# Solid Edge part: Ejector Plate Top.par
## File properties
Author: davee
Template: Normal.par
Last saved by: davee
Revision: 9
Application: Solid Edge
Accuracy: 0.990
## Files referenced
..\Loose Support Mould.asm
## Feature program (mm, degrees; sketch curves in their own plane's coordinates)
sketch for "unnamed Protrusion 1" plane through (0, 0, 0) normal (0, 0, 1) x-axis (1, 0, 0)
  line (-62.5, -100) -> (62.5, -100)
  line (62.5, -100) -> (62.5, 100)
  line (62.5, 100) -> (-62.5, 100)
  line (-62.5, 100) -> (-62.5, -100)
  dimension (linear) = 62.5
  dimension (linear) = 62.5
extrude "unnamed Protrusion 1" add finite 16 along -normal
sketch for "Hole_1" plane through (0, 0, 0) normal (0, 0, 1) x-axis (1, 0, 0)
  hole centre (54, 89) bore radius 2.4585
hole "Hole_1" through  ThreadDepth = 2 mm
sketch for "unnamed Hole 1" plane through (0, 0, 0) normal (0, 0, 1) x-axis (1, 0, 0)
  hole centre (54, -89) bore radius 2.4585
hole "unnamed Hole 1" through
sketch for "unnamed Hole 2" plane through (0, 0, 0) normal (0, 0, 1) x-axis (1, 0, 0)
  hole centre (-54, -89) bore radius 2.4585
hole "unnamed Hole 2" through
sketch for "unnamed Hole 3" plane through (0, 0, 0) normal (0, 0, 1) x-axis (1, 0, 0)
  hole centre (-54, 89) bore radius 2.4585
  dimension (linear) = 54
hole "unnamed Hole 3" through
pattern "unnamed Pattern 1" of "Hole_1", "unnamed Hole 1", "unnamed Hole 2", "unnamed Hole 3"
sketch for "Hole_5" plane through (0, 0, -16) normal (0, 0, -1) x-axis (-1, 0, 0)
  hole centre (0, 0) bore radius 3.25
hole "Hole_5" diameter 6.5 through  CounterBoreDepth = 5.05 mm; VBottomAngle = 118 deg
sketch for "ExtrudedCutout_1" plane through (0, 0, 0) normal (0, 0, 1) x-axis (-1, 0, 0)
extrude "ExtrudedCutout_1" cut finite 66.675 along -normal
sketch for "Hole_11" plane through (0, 0, -16) normal (0, 0, -1) x-axis (-1, 0, 0)
  hole centre (-40, 85) bore radius 5.25
hole "Hole_11" diameter 10.5 through  CounterBoreDepth = 5.05 mm; VBottomAngle = 118 deg
sketch for "unnamed Hole 4" plane through (0, 0, -16) normal (0, 0, -1) x-axis (-1, 0, 0)
  hole centre (40, 85) bore radius 5.25
hole "unnamed Hole 4" through
sketch for "unnamed Hole 5" plane through (0, 0, -16) normal (0, 0, -1) x-axis (-1, 0, 0)
  hole centre (40, -85) bore radius 5.25
hole "unnamed Hole 5" through
sketch for "unnamed Hole 6" plane through (0, 0, -16) normal (0, 0, -1) x-axis (-1, 0, 0)
  hole centre (-40, -85) bore radius 5.25
hole "unnamed Hole 6" through
sketch for "Hole_15" plane through (0, 0, -16) normal (0, 0, -1) x-axis (-1, 0, 0)
  hole centre (-22, 13) bore radius 3.25
hole "Hole_15" diameter 6.5 through  CounterBoreDepth = 5.05 mm; VBottomAngle = 118 deg
sketch for "unnamed Hole 7" plane through (0, 0, -16) normal (0, 0, -1) x-axis (-1, 0, 0)
  hole centre (22, 13) bore radius 3.25
hole "unnamed Hole 7" through
sketch for "Hole_17" plane through (0, 0, -16) normal (0, 0, -1) x-axis (-1, 0, 0)
  hole centre (-25.3, 74) bore radius 1.75
hole "Hole_17" diameter 3.5 through  CounterBoreDepth = 3.05 mm; VBottomAngle = 118 deg
sketch for "unnamed Hole 8" plane through (0, 0, -16) normal (0, 0, -1) x-axis (-1, 0, 0)
  hole centre (-13.1725, 74) bore radius 1.75
hole "unnamed Hole 8" through
sketch for "unnamed Hole 9" plane through (0, 0, -16) normal (0, 0, -1) x-axis (-1, 0, 0)
  hole centre (13.172, 74) bore radius 1.75
hole "unnamed Hole 9" through
sketch for "unnamed Hole 10" plane through (0, 0, -16) normal (0, 0, -1) x-axis (-1, 0, 0)
  hole centre (25.3, 74) bore radius 1.75
hole "unnamed Hole 10" through
pattern "unnamed Pattern 2" of "Hole_11", "unnamed Hole 4", "unnamed Hole 5", "unnamed Hole 6"
pattern "unnamed Pattern 3" of "Hole_15", "unnamed Hole 7"
pattern "unnamed Pattern 4" of "Hole_17", "unnamed Hole 8", "unnamed Hole 9", "unnamed Hole 10"
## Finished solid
Body 1: solid body, 44 faces, 66 edges, 8 vertices.
  Faces by surface: cylinder 27, plane 17
  Edges by curve: circle 54, line 12
Bounding box of the edges (mm): 125.000 x 200.000 x 16.000, from (-62.5, -100, -16) to (62.5, 100, 0).
Cylindrical faces by radius (mm): R1.75 x4, R2.4585 x4, R3 x1, R3.25 x3, R3.5 x4, R5.25 x4, R6.5 x3, R8.5 x4
Planar faces by outward normal: +x 1, +y 1, +z 1, -x 1, -y 1, -z 12
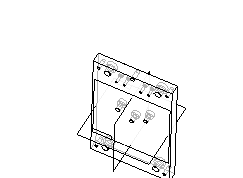
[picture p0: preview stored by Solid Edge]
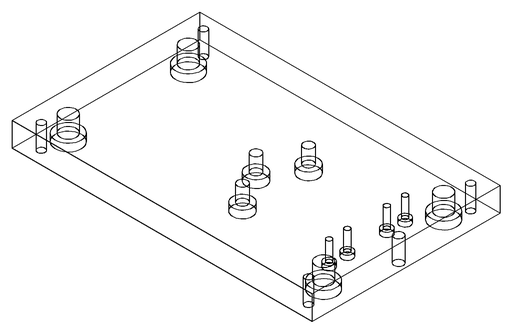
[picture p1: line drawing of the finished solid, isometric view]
